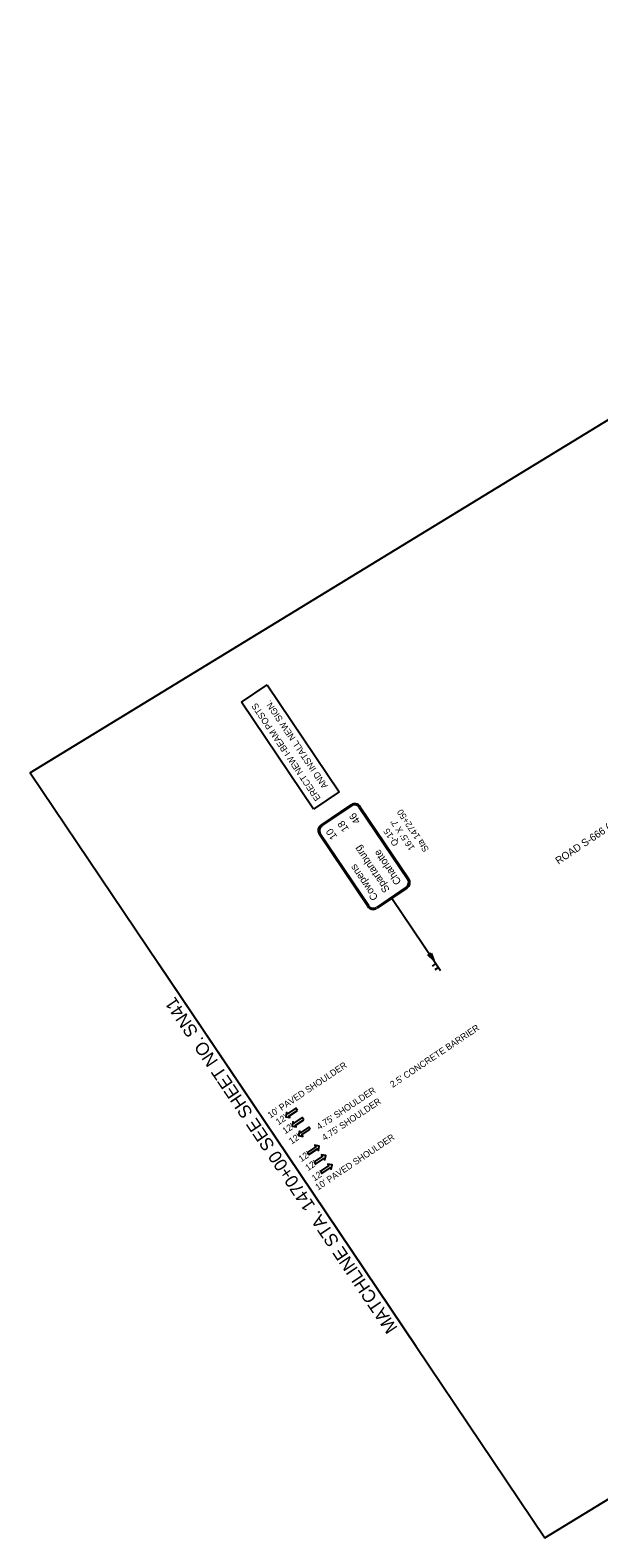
# Model space of a CAD drawing. Extents: x 1794441 to 1796169, y 1186590 to 1188248.
# Drawn here: x 1794441 to 1795059, y 1186590 to 1188227 of the extents above; entities that cross this region are included whole.
import ezdxf

# ---------------------------------------------------------------- set-up
doc = ezdxf.new("R2010")
doc.units = 0
for name, color, linetype in [('RD_PD_Final_LnLine', 7, 'Continuous'), ('RD_PD_Final_TX', 7, 'Continuous'), ('RD_SHT_MatchLine', 7, 'Continuous'), ('RD_SHT_ShtClip', 7, 'Continuous'), ('RD_TX_RoadID', 7, 'Continuous'), ('SN_P_Signs', 7, 'Continuous')]:
    doc.layers.add(name, color=color, linetype=linetype)

# ---------------------------------------------------------------- blocks, each defined once
blk = doc.blocks.new('SARRW2')
at = {"layer": 'RD_PD_Final_LnLine'}
blk.add_lwpolyline([(-12, 1.2), (-12, -1.2), (-2.8, -1.2), (-2.8, -2.8), (0, 0), (-2.8, 2.8), (-2.8, 1.2)], close=True, dxfattribs=at)

msp = doc.modelspace()

# ---------------------------------------------------------------- linework, layer by layer
at = {"layer": 'RD_SHT_MatchLine'}
msp.add_lwpolyline([(1794860.5, 1186798.2), (1794720.8, 1187005.6), (1794581.2, 1187213)], dxfattribs=at)
at = {"layer": 'RD_SHT_ShtClip'}
msp.add_lwpolyline([(1795576.3, 1186941.8), (1795521.6, 1187031.4), (1796168.8, 1187426.2), (1796102.9, 1187566.3), (1795893.4, 1188012.1), (1795762.4, 1188226.7), (1794441.4, 1187420.8), (1794720.8, 1187005.6), (1795000.3, 1186590.4)], close=True, dxfattribs=at)
at = {"layer": 'SN_P_Signs'}
for p, q in [((1794670.8, 1187497.5), (1794698.7, 1187516.2)), ((1794698.7, 1187516.2), (1794776.9, 1187400.1)), ((1794749, 1187381.3), (1794670.8, 1187497.5)), ((1794776.9, 1187400.1), (1794749, 1187381.3)), ((1794808.1, 1187275.7), (1794755.4, 1187354)), ((1794809.1, 1187276.4), (1794756.4, 1187354.6)), ((1794834.3, 1187284.7), (1794879.9, 1187217)), ((1794882.1, 1187213.7), (1794878, 1187211)), ((1794879.9, 1187217), (1794887.2, 1187206.2)), ((1794884.9, 1187209.6), (1794880.8, 1187206.8))]:
    msp.add_line(p, q, dxfattribs=at)
for points in [[(1794757.3, 1187363.9), (1794789.9, 1187385.9)], [(1794758, 1187363), (1794790.6, 1187384.9)], [(1794798.9, 1187383.2), (1794851.6, 1187305)], [(1794799.9, 1187383.9), (1794852.6, 1187305.7)], [(1794849.9, 1187296.7), (1794817.4, 1187274.7)], [(1794850.6, 1187295.7), (1794818.1, 1187273.7)]]:
    msp.add_lwpolyline(points, dxfattribs=at)
msp.add_lwpolyline([(1794877, 1187224.9), (1794879.9, 1187217), (1794873.6, 1187222.7)], close=True, dxfattribs=at)
for centre, radius, start, end in [((1794793.9, 1187379.9), 7.2, 33.9476, 123.9476), ((1794793.9, 1187379.9), 6, 33.9476, 123.9476), ((1794761.4, 1187358), 7.2, 123.9476, 213.9476), ((1794761.4, 1187358), 6, 123.9476, 213.9476), ((1794846.6, 1187301.6), 6, 303.9476, 33.9476), ((1794846.6, 1187301.6), 7.2, 303.9476, 33.9476), ((1794814, 1187279.7), 7.2, 213.9476, 303.9476), ((1794814, 1187279.7), 6, 213.9476, 303.9476)]:
    msp.add_arc(centre, radius, start, end, dxfattribs=at)

# ---------------------------------------------------------------- block references
at = {"layer": 'RD_PD_Final_LnLine'}
for p, xscale, yscale, rotation in [((1794718.9, 1187047.4), 1.2, 1.2000000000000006, -145.685794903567), ((1794725.8, 1187037.3), 1.2, 1.2000000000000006, -145.685794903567), ((1794732.9, 1187027), 1.2, 1.2000000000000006, -145.685794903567), ((1794755.3, 1187015.6), 1.1999999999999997, 1.2000000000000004, 34.314205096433), ((1794762.4, 1187005.3), 1.1999999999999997, 1.2000000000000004, 34.314205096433), ((1794769.3, 1186995.2), 1.1999999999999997, 1.2000000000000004, 34.314205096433)]:
    msp.add_blockref('SARRW2', p, dxfattribs=dict(at, xscale=xscale, yscale=yscale, rotation=rotation))

# ---------------------------------------------------------------- texts
at = {"layer": 'RD_PD_Final_TX'}
for s, rotation, p in [("2.5' CONCRETE BARRIER", 33.8271, (1794835.2, 1187078.7)), ("10' PAVED SHOULDER", 33.8271, (1794702.2, 1187045.4)), ("4.75' SHOULDER", 33.8271, (1794755.4, 1187032.9)), ("4.75' SHOULDER", 33.8271, (1794761.2, 1187021)), ("12'", 34.3142, (1794711.1, 1187038)), ("12'", 34.3142, (1794718.4, 1187028.4)), ("12'", 34.3142, (1794725.4, 1187017.2)), ("10' PAVED SHOULDER", 33.8643, (1794754, 1186967.2)), ("12'", 34.3142, (1794735.9, 1186998)), ("12'", 34.3142, (1794743.2, 1186988.3)), ("12'", 34.3142, (1794750.2, 1186977.1))]:
    msp.add_text(s, height=7, rotation=rotation, dxfattribs=at).set_placement(p)
at = {"layer": 'RD_SHT_MatchLine'}
msp.add_text('MATCHLINE STA. 1470+00 SEE SHEET NO. SN41', height=14, rotation=123.9476, dxfattribs=at).set_placement((1794841, 1186818.2))
at = {"layer": 'RD_TX_RoadID'}
msp.add_text('ROAD S-666 (PEACHOID RD)', height=8, rotation=33.8393, dxfattribs=at).set_placement((1795015.2, 1187321))
at = {"layer": 'SN_P_Signs'}
for s, height, rotation, p in [('ERECT NEW I-BEAM POSTS', 7, 123.9477, (1794757.2, 1187393.1)), ('AND INSTALL NEW SIGN.', 7, 123.9477, (1794765.1, 1187406.5)), ('46', 8, 123.9476, (1794800.5, 1187368.3)), ('Sta 1472+50', 7, 123.9477, (1794874.9, 1187337.7)), ('10', 8, 123.9476, (1794775.3, 1187351.4)), ('18', 8, 123.9476, (1794787.9, 1187359.8)), ('Q-15', 7, 123.9477, (1794842, 1187344)), ("16.5' X 7'", 7, 123.9477, (1794859.5, 1187339.3)), ('Spartanburg', 8, 123.9476, (1794832.3, 1187293.9)), ('Charlotte', 8, 123.9476, (1794844.9, 1187302.4)), ('Cowpens', 8, 123.9476, (1794819.7, 1187285.4))]:
    msp.add_text(s, height=height, rotation=rotation, dxfattribs=at).set_placement(p)

doc.saveas('drawing.dxf')
